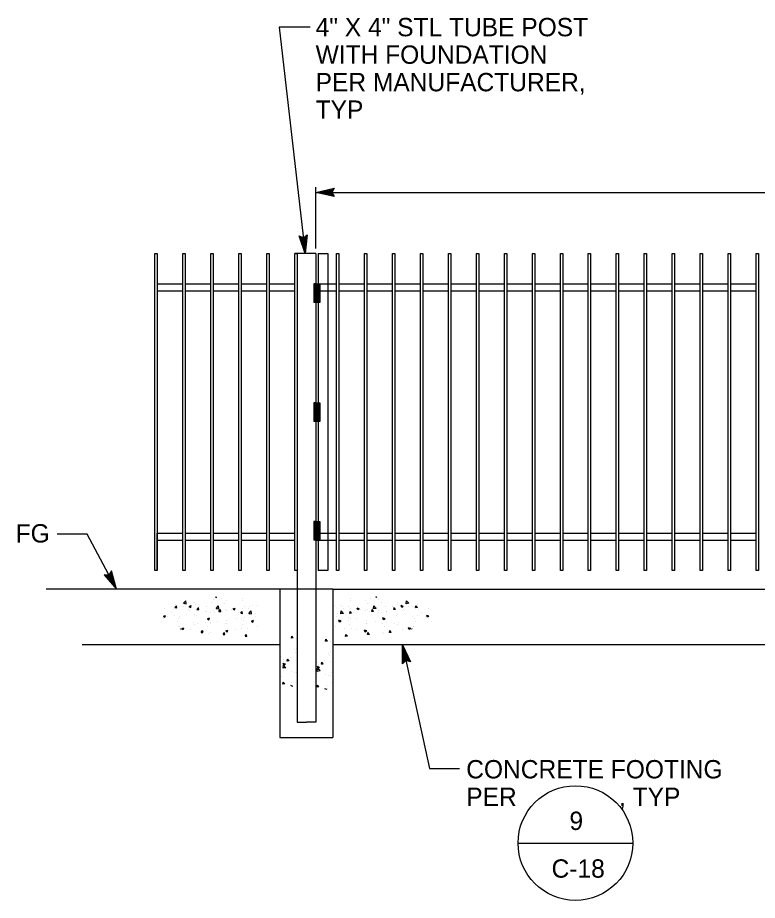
# Model space of a CAD drawing. Extents: x -121933 to -117742, y -103160 to -100084.
# Drawn here: x -118898.2 to -118656.4, y -103159.5 to -102870.8 of the extents above; entities that cross this region are included whole.
import ezdxf

# ---------------------------------------------------------------- set-up
doc = ezdxf.new("R2010")
doc.units = 0
for name, color, linetype in [('Erosion C (Lv35)', 7, 'Continuous'), ('G-MARK', 7, 'Continuous'), ('Misc CnstDet(22)', 7, 'Continuous')]:
    doc.layers.add(name, color=color, linetype=linetype)

# ---------------------------------------------------------------- blocks, each defined once
blk = doc.blocks.new('SC8415')
at = {"layer": 'Erosion C (Lv35)'}
for p, q in [((-1.69606, 1.76963), (-1.69579, 1.76945)), ((-1.69579, 1.76945), (-1.69573, 1.76963)), ((-1.69408, 1.76913), (-1.69408, 1.76913)), ((-1.68715, 1.76926), (-1.68715, 1.76926)), ((-1.70955, 1.76614), (-1.70906, 1.76672)), ((-1.70955, 1.76614), (-1.70894, 1.76608)), ((-1.70943, 1.76711), (-1.70943, 1.76711)), ((-1.70894, 1.76609), (-1.70906, 1.76672)), ((-1.70791, 1.76649), (-1.70791, 1.76649)), ((-1.70689, 1.76745), (-1.70689, 1.76745)), ((-1.70672, 1.76656), (-1.70672, 1.76656)), ((-1.70669, 1.76754), (-1.7059, 1.76836)), ((-1.70669, 1.76754), (-1.70579, 1.7674)), ((-1.70579, 1.7674), (-1.7059, 1.76836)), ((-1.70484, 1.76651), (-1.70412, 1.76679)), ((-1.70484, 1.76651), (-1.70433, 1.76617)), ((-1.70433, 1.76617), (-1.70412, 1.76679)), ((-1.70304, 1.76795), (-1.70304, 1.76795)), ((-1.70278, 1.76714), (-1.70278, 1.76714)), ((-1.70226, 1.7655), (-1.70177, 1.76608)), ((-1.70165, 1.76545), (-1.70177, 1.76609)), ((-1.7013, 1.76633), (-1.7013, 1.76633)), ((-1.69901, 1.76659), (-1.69901, 1.76659)), ((-1.6975, 1.7679), (-1.6975, 1.7679)), ((-1.69662, 1.7688), (-1.69662, 1.7688)), ((-1.69588, 1.7661), (-1.69588, 1.7661)), ((-1.69585, 1.76586), (-1.69506, 1.76668)), ((-1.69494, 1.76572), (-1.69506, 1.76668)), ((-1.69309, 1.7676), (-1.69309, 1.7676)), ((-1.69228, 1.76861), (-1.69228, 1.76861)), ((-1.68716, 1.76862), (-1.68716, 1.76862)), ((-1.68649, 1.76648), (-1.68649, 1.76648)), ((-1.68473, 1.76639), (-1.68473, 1.76639)), ((-1.68394, 1.76681), (-1.68394, 1.76681)), ((-1.682, 1.76664), (-1.682, 1.76664)), ((-1.71337, 1.76324), (-1.71266, 1.76351)), ((-1.71337, 1.76324), (-1.71287, 1.7629)), ((-1.71312, 1.76577), (-1.71312, 1.76577)), ((-1.71287, 1.7629), (-1.71266, 1.76351)), ((-1.7121, 1.7631), (-1.7121, 1.7631)), ((-1.71086, 1.76455), (-1.71086, 1.76455)), ((-1.71, 1.76543), (-1.71, 1.76543)), ((-1.70956, 1.76344), (-1.70956, 1.76344)), ((-1.70803, 1.7631), (-1.70803, 1.7631)), ((-1.70571, 1.76395), (-1.70571, 1.76395)), ((-1.70494, 1.76557), (-1.70494, 1.76557)), ((-1.70458, 1.7652), (-1.70458, 1.7652)), ((-1.7029, 1.76375), (-1.7029, 1.76375)), ((-1.7025, 1.76334), (-1.7025, 1.76334)), ((-1.70226, 1.7655), (-1.70165, 1.76545)), ((-1.6993, 1.76479), (-1.6993, 1.76479)), ((-1.69916, 1.76497), (-1.69916, 1.76497)), ((-1.69762, 1.76452), (-1.69762, 1.76452)), ((-1.69675, 1.76513), (-1.69675, 1.76513)), ((-1.69658, 1.76435), (-1.69658, 1.76435)), ((-1.69585, 1.76586), (-1.69494, 1.76572)), ((-1.69497, 1.76486), (-1.69449, 1.76545)), ((-1.69497, 1.76486), (-1.69437, 1.76481)), ((-1.69437, 1.76481), (-1.69448, 1.76545)), ((-1.69373, 1.76474), (-1.69373, 1.76474)), ((-1.6929, 1.76563), (-1.6929, 1.76563)), ((-1.69241, 1.76523), (-1.69241, 1.76523)), ((-1.69065, 1.76537), (-1.69065, 1.76537)), ((-1.69045, 1.76587), (-1.69045, 1.76587)), ((-1.69023, 1.7657), (-1.68952, 1.76597)), ((-1.69023, 1.7657), (-1.68973, 1.76536)), ((-1.68973, 1.76536), (-1.68952, 1.76597)), ((-1.68831, 1.76451), (-1.68831, 1.76451)), ((-1.68769, 1.76423), (-1.6872, 1.76481)), ((-1.68769, 1.76423), (-1.68708, 1.76417)), ((-1.68727, 1.76588), (-1.68727, 1.76588)), ((-1.68708, 1.76417), (-1.6872, 1.76481)), ((-1.68503, 1.76565), (-1.68503, 1.76565)), ((-1.685, 1.76418), (-1.68421, 1.765)), ((-1.685, 1.76418), (-1.6841, 1.76404)), ((-1.6841, 1.76404), (-1.68421, 1.765)), ((-1.68289, 1.76428), (-1.68289, 1.76428)), ((-1.68277, 1.76331), (-1.68277, 1.76331)), ((-1.71417, 1.76163), (-1.71417, 1.76163)), ((-1.71325, 1.76239), (-1.71325, 1.76239)), ((-1.70874, 1.7614), (-1.70874, 1.7614)), ((-1.70843, 1.76232), (-1.70843, 1.76232)), ((-1.70332, 1.76117), (-1.70332, 1.76117)), ((-1.70302, 1.76037), (-1.70302, 1.76037)), ((-1.70197, 1.76078), (-1.70197, 1.76078)), ((-1.69943, 1.76112), (-1.69943, 1.76112)), ((-1.69877, 1.76242), (-1.69806, 1.7627)), ((-1.69877, 1.76242), (-1.69827, 1.76208)), ((-1.69826, 1.76208), (-1.69806, 1.7627)), ((-1.6979, 1.76094), (-1.6979, 1.76094)), ((-1.69775, 1.76113), (-1.69775, 1.76113)), ((-1.69558, 1.76162), (-1.69558, 1.76162)), ((-1.6927, 1.7608), (-1.6927, 1.7608)), ((-1.69253, 1.76185), (-1.69253, 1.76185)), ((-1.69247, 1.76071), (-1.69247, 1.76071)), ((-1.68916, 1.76247), (-1.68916, 1.76247)), ((-1.6874, 1.7625), (-1.6874, 1.7625)), ((-1.68705, 1.76048), (-1.68705, 1.76048)), ((-1.68677, 1.76182), (-1.68677, 1.76182)), ((-1.68662, 1.7628), (-1.68662, 1.7628)), ((-1.68417, 1.76161), (-1.68346, 1.76188)), ((-1.68417, 1.76161), (-1.68366, 1.76127)), ((-1.68366, 1.76127), (-1.68346, 1.76188)), ((-1.70839, 1.75994), (-1.70839, 1.75994)), ((-1.70815, 1.75972), (-1.70815, 1.75972)), ((-1.70775, 1.75896), (-1.70765, 1.75908)), ((-1.70762, 1.7589), (-1.70765, 1.75908)), ((-1.70731, 1.75915), (-1.7066, 1.75942)), ((-1.70731, 1.75915), (-1.7068, 1.75881)), ((-1.7068, 1.75881), (-1.7066, 1.75942)), ((-1.70455, 1.75876), (-1.70455, 1.75876)), ((-1.70085, 1.75786), (-1.70036, 1.75844)), ((-1.70085, 1.75786), (-1.70025, 1.7578)), ((-1.70024, 1.75781), (-1.70036, 1.75844)), ((-1.69862, 1.75978), (-1.69862, 1.75978)), ((-1.69825, 1.75762), (-1.69825, 1.75762)), ((-1.69787, 1.75775), (-1.69787, 1.75775)), ((-1.69357, 1.75722), (-1.69308, 1.7578)), ((-1.69296, 1.75717), (-1.69307, 1.75781)), ((-1.69271, 1.75833), (-1.692, 1.75861)), ((-1.69271, 1.75833), (-1.6922, 1.75799)), ((-1.69265, 1.75847), (-1.69265, 1.75847)), ((-1.6922, 1.75799), (-1.69199, 1.75861)), ((-1.69183, 1.75846), (-1.69183, 1.75846)), ((-1.68929, 1.7588), (-1.68929, 1.7588)), ((-1.68752, 1.75912), (-1.68752, 1.75912)), ((-1.68544, 1.7593), (-1.68544, 1.7593)), ((-1.68224, 1.75988), (-1.68224, 1.75988)), ((-1.69357, 1.75722), (-1.69296, 1.75717)), ((-1.68628, 1.75658), (-1.68579, 1.75717)), ((-1.68628, 1.75658), (-1.68567, 1.75653)), ((-1.68567, 1.75653), (-1.68579, 1.75717))]:
    blk.add_line(p, q, dxfattribs=at)

msp = doc.modelspace()

# ---------------------------------------------------------------- linework, layer by layer
at = {"layer": 'G-MARK'}
for p, q in [((-118802.55, -102873.86), (-118812.69, -102873.86)), ((-118812.69, -102873.86), (-118804.14, -102947.98)), ((-118800.69, -102946.27), (-118800.69, -102926.23)), ((-118800.69, -102927.94), (-118794.69, -102926.61)), ((-118799.3, -102927.94), (-118794.92, -102926.97)), ((-118797.93, -102927.94), (-118795.1, -102927.32)), ((-118794.69, -102926.61), (-118795.49, -102927.94)), ((-118794.69, -102926.61), (-118794.69, -102926.61)), ((-118800.69, -102927.94), (-118459.12, -102927.94)), ((-118794.69, -102929.28), (-118800.69, -102927.94)), ((-118800.69, -102927.94), (-118800.69, -102927.94)), ((-118800.69, -102927.94), (-118456.45, -102927.94)), ((-118794.91, -102928.93), (-118799.31, -102927.94)), ((-118795.14, -102928.57), (-118797.93, -102927.94)), ((-118796.55, -102927.95), (-118795.34, -102927.68)), ((-118795.32, -102928.22), (-118796.55, -102927.95)), ((-118795.49, -102927.94), (-118794.69, -102929.28)), ((-118794.69, -102929.28), (-118794.69, -102929.28)), ((-118804.74, -102942.82), (-118803.5, -102941.87)), ((-118803.5, -102941.87), (-118804.14, -102947.98)), ((-118803.5, -102941.87), (-118803.5, -102941.87)), ((-118804.14, -102947.98), (-118806.15, -102942.17)), ((-118806.15, -102942.17), (-118806.15, -102942.17)), ((-118806.15, -102942.17), (-118804.74, -102942.82)), ((-118804.31, -102946.6), (-118805.77, -102942.37)), ((-118804.46, -102945.24), (-118805.4, -102942.5)), ((-118804.61, -102943.86), (-118805.02, -102942.69)), ((-118804.48, -102942.61), (-118804.61, -102943.86)), ((-118804.16, -102942.4), (-118804.46, -102945.24)), ((-118803.83, -102942.12), (-118804.3, -102946.61)), ((-118804.14, -102947.98), (-118804.14, -102947.98)), ((-118875.41, -103039.76), (-118885.2, -103039.76)), ((-118865.89, -103057.71), (-118875.41, -103039.76)), ((-118867.53, -103051.79), (-118868.33, -103053.12)), ((-118865.89, -103057.71), (-118867.53, -103051.79)), ((-118867.53, -103051.79), (-118867.53, -103051.79)), ((-118868.33, -103053.12), (-118869.89, -103053.04)), ((-118869.89, -103053.04), (-118869.89, -103053.04)), ((-118869.89, -103053.04), (-118865.89, -103057.71)), ((-118869.47, -103053.06), (-118866.54, -103056.49)), ((-118869.04, -103053.1), (-118867.19, -103055.27)), ((-118868.66, -103053.09), (-118867.84, -103054.05)), ((-118867.84, -103054.05), (-118868.17, -103052.86)), ((-118867.19, -103055.27), (-118867.96, -103052.48)), ((-118866.54, -103056.48), (-118867.74, -103052.16)), ((-118865.89, -103057.71), (-118865.89, -103057.71)), ((-118772.38, -103082.15), (-118772.36, -103076)), ((-118772.36, -103076), (-118763.49, -103116.38)), ((-118772.36, -103076), (-118772.36, -103076)), ((-118772.36, -103076), (-118769.77, -103081.57)), ((-118772.08, -103081.86), (-118772.06, -103077.35)), ((-118772.06, -103077.36), (-118770.17, -103081.42)), ((-118771.78, -103081.55), (-118771.77, -103078.7)), ((-118771.77, -103078.7), (-118770.55, -103081.32)), ((-118771.48, -103081.31), (-118771.47, -103080.05)), ((-118771.47, -103080.05), (-118770.95, -103081.17)), ((-118771.24, -103081.08), (-118772.38, -103082.15)), ((-118772.38, -103082.15), (-118772.38, -103082.15)), ((-118769.77, -103081.57), (-118771.24, -103081.08)), ((-118769.77, -103081.57), (-118769.77, -103081.57)), ((-118763.49, -103116.38), (-118753.69, -103116.38)), ((-118734.78, -103140.84), (-118697.08, -103140.84))]:
    msp.add_line(p, q, dxfattribs=at)
msp.add_circle((-118715.83, -103140.79), 18.75, dxfattribs=at)
at = {"layer": 'Misc CnstDet(22)'}
for p, q in [((-118853.29, -102947.98), (-118853.29, -102947.98)), ((-118843.76, -102947.98), (-118843.76, -102947.98)), ((-118834.62, -102947.98), (-118834.62, -102947.98)), ((-118800.72, -102947.98), (-118807.57, -102947.98)), ((-118807.19, -102947.98), (-118807.19, -102947.98)), ((-118800.72, -102947.98), (-118800.72, -103101.22)), ((-118799.92, -102947.98), (-118799.92, -103007.42)), ((-118799.92, -102947.98), (-118796.77, -102947.98)), ((-118796.77, -102947.98), (-118796.77, -103007.42)), ((-118852.53, -102957.89), (-118844.15, -102957.89)), ((-118843.38, -102957.89), (-118835, -102957.89)), ((-118834.24, -102957.89), (-118825.86, -102957.89)), ((-118825.1, -102957.89), (-118816.71, -102957.89)), ((-118815.95, -102957.89), (-118807.57, -102957.89)), ((-118801.35, -102957.89), (-118801.35, -102963.99)), ((-118800.75, -102957.89), (-118801.35, -102957.89)), ((-118801.15, -102957.89), (-118801.15, -102963.99)), ((-118800.95, -102957.89), (-118800.95, -102963.99)), ((-118800.75, -102957.89), (-118800.75, -102963.99)), ((-118800.72, -102957.89), (-118793.91, -102957.89)), ((-118793.15, -102957.89), (-118784.77, -102957.89)), ((-118784.01, -102957.89), (-118775.63, -102957.89)), ((-118774.86, -102957.89), (-118766.48, -102957.89)), ((-118765.72, -102957.89), (-118757.34, -102957.89)), ((-118756.58, -102957.89), (-118748.19, -102957.89)), ((-118747.43, -102957.89), (-118739.05, -102957.89)), ((-118738.29, -102957.89), (-118729.91, -102957.89)), ((-118729.14, -102957.89), (-118720.76, -102957.89)), ((-118720, -102957.89), (-118711.62, -102957.89)), ((-118710.86, -102957.89), (-118702.47, -102957.89)), ((-118701.71, -102957.89), (-118693.33, -102957.89)), ((-118692.57, -102957.89), (-118684.19, -102957.89)), ((-118683.42, -102957.89), (-118675.04, -102957.89)), ((-118674.28, -102957.89), (-118665.9, -102957.89)), ((-118665.14, -102957.89), (-118656.75, -102957.89)), ((-118852.53, -102960.17), (-118844.15, -102960.17)), ((-118843.38, -102960.17), (-118835, -102960.17)), ((-118834.24, -102960.17), (-118825.86, -102960.17)), ((-118825.1, -102960.17), (-118816.71, -102960.17)), ((-118815.95, -102960.17), (-118807.57, -102960.17)), ((-118806.81, -102960.17), (-118806.81, -103101.22)), ((-118800.72, -102960.17), (-118793.91, -102960.17)), ((-118793.15, -102960.17), (-118784.77, -102960.17)), ((-118784.01, -102960.17), (-118775.63, -102960.17)), ((-118774.86, -102960.17), (-118766.48, -102960.17)), ((-118765.72, -102960.17), (-118757.34, -102960.17)), ((-118756.58, -102960.17), (-118748.19, -102960.17)), ((-118747.43, -102960.17), (-118739.05, -102960.17)), ((-118738.29, -102960.17), (-118729.91, -102960.17)), ((-118729.14, -102960.17), (-118720.76, -102960.17)), ((-118720, -102960.17), (-118711.62, -102960.17)), ((-118710.86, -102960.17), (-118702.47, -102960.17)), ((-118701.71, -102960.17), (-118693.33, -102960.17)), ((-118692.57, -102960.17), (-118684.19, -102960.17)), ((-118683.42, -102960.17), (-118675.04, -102960.17)), ((-118674.28, -102960.17), (-118665.9, -102960.17)), ((-118665.14, -102960.17), (-118656.75, -102960.17)), ((-118800.75, -102963.99), (-118801.35, -102963.99)), ((-118801.35, -102996.75), (-118801.35, -103002.85)), ((-118800.75, -102996.75), (-118801.35, -102996.75)), ((-118801.15, -102996.75), (-118801.15, -103002.85)), ((-118800.95, -102996.75), (-118800.95, -103002.85)), ((-118800.75, -102996.75), (-118800.75, -103002.85)), ((-118800.75, -103002.85), (-118801.35, -103002.85)), ((-118799.92, -103007.42), (-118799.92, -103051.61)), ((-118801.35, -103035.61), (-118801.35, -103041.71)), ((-118800.75, -103035.61), (-118801.35, -103035.61)), ((-118801.15, -103035.61), (-118801.15, -103041.71)), ((-118800.95, -103035.61), (-118800.95, -103041.71)), ((-118800.75, -103035.61), (-118800.75, -103041.71)), ((-118852.53, -103051.61), (-118852.53, -103039.42)), ((-118852.53, -103039.42), (-118844.15, -103039.42)), ((-118843.38, -103039.42), (-118835, -103039.42)), ((-118834.24, -103039.42), (-118825.86, -103039.42)), ((-118825.1, -103039.42), (-118816.71, -103039.42)), ((-118815.95, -103039.42), (-118807.57, -103039.42)), ((-118800.72, -103039.42), (-118793.91, -103039.42)), ((-118793.15, -103039.42), (-118784.77, -103039.42)), ((-118784.01, -103039.42), (-118775.63, -103039.42)), ((-118774.86, -103039.42), (-118766.48, -103039.42)), ((-118765.72, -103039.42), (-118757.34, -103039.42)), ((-118756.58, -103039.42), (-118748.19, -103039.42)), ((-118747.43, -103039.42), (-118739.05, -103039.42)), ((-118738.29, -103039.42), (-118729.91, -103039.42)), ((-118729.14, -103039.42), (-118720.76, -103039.42)), ((-118720, -103039.42), (-118711.62, -103039.42)), ((-118710.86, -103039.42), (-118702.47, -103039.42)), ((-118701.71, -103039.42), (-118693.33, -103039.42)), ((-118692.57, -103039.42), (-118684.19, -103039.42)), ((-118683.42, -103039.42), (-118675.04, -103039.42)), ((-118674.28, -103039.42), (-118665.9, -103039.42)), ((-118665.14, -103039.42), (-118656.75, -103039.42)), ((-118852.53, -103041.71), (-118844.15, -103041.71)), ((-118843.38, -103041.71), (-118835, -103041.71)), ((-118834.24, -103041.71), (-118825.86, -103041.71)), ((-118825.1, -103041.71), (-118816.71, -103041.71)), ((-118815.95, -103041.71), (-118807.57, -103041.71)), ((-118800.75, -103041.71), (-118801.35, -103041.71)), ((-118800.72, -103041.71), (-118793.91, -103041.71)), ((-118793.15, -103041.71), (-118784.77, -103041.71)), ((-118784.01, -103041.71), (-118775.63, -103041.71)), ((-118774.86, -103041.71), (-118766.48, -103041.71)), ((-118765.72, -103041.71), (-118757.34, -103041.71)), ((-118756.58, -103041.71), (-118748.19, -103041.71)), ((-118747.43, -103041.71), (-118739.05, -103041.71)), ((-118738.29, -103041.71), (-118729.91, -103041.71)), ((-118729.14, -103041.71), (-118720.76, -103041.71)), ((-118720, -103041.71), (-118711.62, -103041.71)), ((-118710.86, -103041.71), (-118702.47, -103041.71)), ((-118701.71, -103041.71), (-118693.33, -103041.71)), ((-118692.57, -103041.71), (-118684.19, -103041.71)), ((-118683.42, -103041.71), (-118675.04, -103041.71)), ((-118674.28, -103041.71), (-118665.9, -103041.71)), ((-118665.14, -103041.71), (-118656.75, -103041.71)), ((-118853.29, -103051.61), (-118853.29, -103051.61)), ((-118796.77, -103051.61), (-118799.92, -103051.61)), ((-118812.43, -103057.71), (-118888.83, -103057.71)), ((-118855.01, -103057.71), (-118877.35, -103057.71)), ((-118875.63, -103057.71), (-118875.63, -103057.71)), ((-118855.01, -103057.71), (-118860.95, -103057.71)), ((-118859.24, -103057.71), (-118859.24, -103057.71)), ((-118853.29, -103057.71), (-118853.29, -103057.71)), ((-118853.29, -103057.71), (-118853.29, -103057.71)), ((-118812.43, -103057.71), (-118812.43, -103094.29)), ((-118795.1, -103057.71), (-118812.43, -103057.71)), ((-118795.1, -103057.71), (-118795.1, -103106.29)), ((-118795.1, -103057.71), (-118622.28, -103057.71)), ((-118808.66, -103073.75), (-118808.55, -103073.12)), ((-118808.06, -103073.69), (-118808.66, -103073.75)), ((-118808.06, -103073.69), (-118808.55, -103073.12)), ((-118807.17, -103073.89), (-118807.17, -103073.89)), ((-118797.49, -103074.76), (-118797.38, -103074.13)), ((-118796.89, -103074.71), (-118797.49, -103074.76)), ((-118796.89, -103074.71), (-118797.37, -103074.13)), ((-118796, -103074.91), (-118796, -103074.91)), ((-118812.43, -103076), (-118877.12, -103076)), ((-118812.24, -103076.47), (-118812.24, -103076.47)), ((-118807.6, -103077.64), (-118807.6, -103077.64)), ((-118807.05, -103077.22), (-118807.05, -103077.22)), ((-118795.27, -103075.21), (-118795.27, -103075.21)), ((-118623.66, -103076), (-118795.1, -103076)), ((-118812.12, -103079.8), (-118812.12, -103079.8)), ((-118810.05, -103081.27), (-118809.93, -103080.64)), ((-118809.45, -103081.22), (-118809.93, -103080.64)), ((-118809.72, -103080.57), (-118809.72, -103080.57)), ((-118809.04, -103080.04), (-118809.04, -103080.04)), ((-118807.33, -103078.38), (-118807.33, -103078.38)), ((-118806.93, -103080.55), (-118806.93, -103080.55)), ((-118796.43, -103078.65), (-118796.43, -103078.65)), ((-118796.16, -103079.39), (-118796.16, -103079.39)), ((-118795.88, -103078.24), (-118795.88, -103078.24)), ((-118812, -103083.13), (-118812, -103083.13)), ((-118811.39, -103083.61), (-118811.28, -103082.66)), ((-118810.5, -103083.48), (-118811.39, -103083.61)), ((-118811.13, -103082.64), (-118811.34, -103082.04)), ((-118810.63, -103082.31), (-118811.33, -103082.04)), ((-118811.29, -103080.75), (-118811.29, -103080.75)), ((-118810.5, -103083.48), (-118811.28, -103082.66)), ((-118811.15, -103081.38), (-118811.15, -103081.38)), ((-118810.63, -103082.31), (-118811.13, -103082.64)), ((-118809.45, -103081.22), (-118810.05, -103081.27)), ((-118799.46, -103083.32), (-118800.16, -103083.05)), ((-118799.96, -103083.65), (-118800.16, -103083.05)), ((-118800.11, -103081.76), (-118800.11, -103081.76)), ((-118799.98, -103082.4), (-118799.98, -103082.4)), ((-118799.46, -103083.32), (-118799.96, -103083.66)), ((-118798.88, -103082.28), (-118798.76, -103081.65)), ((-118798.28, -103082.23), (-118798.88, -103082.28)), ((-118798.28, -103082.23), (-118798.76, -103081.66)), ((-118798.55, -103081.59), (-118798.55, -103081.59)), ((-118797.87, -103081.05), (-118797.87, -103081.05)), ((-118795.76, -103081.57), (-118795.76, -103081.57)), ((-118812.39, -103085.35), (-118812.39, -103085.35)), ((-118811.88, -103086.46), (-118811.88, -103086.46)), ((-118811.16, -103084.37), (-118811.16, -103084.37)), ((-118808.65, -103084.69), (-118808.65, -103084.69)), ((-118807.71, -103085.07), (-118807.71, -103085.07)), ((-118807.06, -103085.12), (-118807.06, -103085.12)), ((-118806.81, -103083.88), (-118806.81, -103083.88)), ((-118800.22, -103084.63), (-118800.11, -103083.68)), ((-118799.33, -103084.49), (-118800.22, -103084.63)), ((-118799.33, -103084.49), (-118800.11, -103083.68)), ((-118799.99, -103085.38), (-118799.99, -103085.38)), ((-118797.48, -103085.71), (-118797.48, -103085.71)), ((-118796.54, -103086.09), (-118796.54, -103086.09)), ((-118795.88, -103086.14), (-118795.88, -103086.14)), ((-118795.63, -103084.89), (-118795.63, -103084.89)), ((-118812.32, -103087.81), (-118812.32, -103087.81)), ((-118811.44, -103088.79), (-118811.32, -103088.16)), ((-118810.84, -103088.74), (-118811.44, -103088.79)), ((-118810.84, -103088.74), (-118811.32, -103088.16)), ((-118808.2, -103089.56), (-118808.9, -103089.29)), ((-118808.53, -103088.31), (-118808.53, -103088.31)), ((-118806.68, -103087.21), (-118806.68, -103087.21)), ((-118800.27, -103089.8), (-118800.15, -103089.18)), ((-118799.67, -103089.75), (-118800.15, -103089.18)), ((-118797.36, -103089.32), (-118797.36, -103089.32)), ((-118795.51, -103088.22), (-118795.51, -103088.22)), ((-118799.67, -103089.75), (-118800.27, -103089.8)), ((-118797.03, -103090.57), (-118797.73, -103090.3)), ((-118812.43, -103094.29), (-118812.43, -103106.29)), ((-118806.81, -103101.22), (-118803.76, -103101.22)), ((-118800.72, -103101.22), (-118803.76, -103101.22)), ((-118812.43, -103106.29), (-118795.1, -103106.29))]:
    msp.add_line(p, q, dxfattribs=at)
for points in [[(-118852.53, -103051.61), (-118853.29, -103051.61), (-118853.29, -102947.98), (-118852.53, -102947.98)], [(-118843.38, -103051.61), (-118844.15, -103051.61), (-118844.15, -102947.98), (-118843.38, -102947.98)], [(-118834.24, -103051.61), (-118835, -103051.61), (-118835, -102947.98), (-118834.24, -102947.98)], [(-118825.1, -103051.61), (-118825.86, -103051.61), (-118825.86, -102947.98), (-118825.1, -102947.98)], [(-118815.95, -103051.61), (-118816.71, -103051.61), (-118816.71, -102947.98), (-118815.95, -102947.98)], [(-118806.81, -103051.61), (-118807.57, -103051.61), (-118807.57, -102947.98), (-118806.81, -102947.98)], [(-118793.15, -103051.61), (-118793.91, -103051.61), (-118793.91, -102947.98), (-118793.15, -102947.98)], [(-118784.01, -103051.61), (-118784.77, -103051.61), (-118784.77, -102947.98), (-118784.01, -102947.98)], [(-118774.86, -103051.61), (-118775.63, -103051.61), (-118775.63, -102947.98), (-118774.86, -102947.98)], [(-118765.72, -103051.61), (-118766.48, -103051.61), (-118766.48, -102947.98), (-118765.72, -102947.98)], [(-118756.58, -103051.61), (-118757.34, -103051.61), (-118757.34, -102947.98), (-118756.58, -102947.98)], [(-118747.43, -103051.61), (-118748.19, -103051.61), (-118748.19, -102947.98), (-118747.43, -102947.98)], [(-118738.29, -103051.61), (-118739.05, -103051.61), (-118739.05, -102947.98), (-118738.29, -102947.98)], [(-118729.14, -103051.61), (-118729.91, -103051.61), (-118729.91, -102947.98), (-118729.14, -102947.98)], [(-118720, -103051.61), (-118720.76, -103051.61), (-118720.76, -102947.98), (-118720, -102947.98)], [(-118710.86, -103051.61), (-118711.62, -103051.61), (-118711.62, -102947.98), (-118710.86, -102947.98)], [(-118701.71, -103051.61), (-118702.47, -103051.61), (-118702.47, -102947.98), (-118701.71, -102947.98)], [(-118692.57, -103051.61), (-118693.33, -103051.61), (-118693.33, -102947.98), (-118692.57, -102947.98)], [(-118683.42, -103051.61), (-118684.19, -103051.61), (-118684.19, -102947.98), (-118683.42, -102947.98)], [(-118674.28, -103051.61), (-118675.04, -103051.61), (-118675.04, -102947.98), (-118674.28, -102947.98)], [(-118665.14, -103051.61), (-118665.9, -103051.61), (-118665.9, -102947.98), (-118665.14, -102947.98)], [(-118655.99, -103051.61), (-118656.75, -103051.61), (-118656.75, -102947.98), (-118655.99, -102947.98)], [(-118799.38, -102963.99), (-118800.75, -102963.99), (-118800.75, -102957.89), (-118799.38, -102957.89)], [(-118799.58, -102963.79), (-118800.55, -102963.79), (-118800.55, -102958.09), (-118799.58, -102958.09)], [(-118799.78, -102963.59), (-118800.35, -102963.59), (-118800.35, -102958.29), (-118799.78, -102958.29)], [(-118799.98, -102963.39), (-118800.15, -102963.39), (-118800.15, -102958.49), (-118799.98, -102958.49)], [(-118799.38, -103002.85), (-118800.75, -103002.85), (-118800.75, -102996.75), (-118799.38, -102996.75)], [(-118799.58, -103002.65), (-118800.55, -103002.65), (-118800.55, -102996.95), (-118799.58, -102996.95)], [(-118799.78, -103002.45), (-118800.35, -103002.45), (-118800.35, -102997.15), (-118799.78, -102997.15)], [(-118799.98, -103002.25), (-118800.15, -103002.25), (-118800.15, -102997.35), (-118799.98, -102997.35)], [(-118799.38, -103041.71), (-118800.75, -103041.71), (-118800.75, -103035.61), (-118799.38, -103035.61)], [(-118799.58, -103041.51), (-118800.55, -103041.51), (-118800.55, -103035.81), (-118799.58, -103035.81)], [(-118799.78, -103041.31), (-118800.35, -103041.31), (-118800.35, -103036.01), (-118799.78, -103036.01)], [(-118799.98, -103041.11), (-118800.15, -103041.11), (-118800.15, -103036.21), (-118799.98, -103036.21)]]:
    msp.add_lwpolyline(points, close=True, dxfattribs=at)
msp.add_lwpolyline([(-118796.77, -103007.42), (-118796.77, -103051.61)], dxfattribs=at)

# ---------------------------------------------------------------- block references
at = {"layer": 'Misc CnstDet(22)', "xscale": 984.251968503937, "yscale": 984.251968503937}
msp.add_blockref('SC8415', (-117164.11, -104802.07), dxfattribs=at)
at = {"layer": 'Misc CnstDet(22)', "xscale": 984.251968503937, "yscale": -984.251968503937, "rotation": 180}
msp.add_blockref('SC8415', (-120450.1, -104802.07), dxfattribs=at)

# ---------------------------------------------------------------- texts
at = {"layer": 'Misc CnstDet(22)'}
for s, p in [('4" X 4" STL TUBE POST ', (-118800.76, -102876.89)), ('WITH FOUNDATION', (-118800.76, -102885.89)), ('PER MANUFACTURER,', (-118800.76, -102894.89)), ('TYP', (-118800.76, -102903.89)), ('FG', (-118898.82, -103042.49)), ('CONCRETE FOOTING', (-118751.53, -103119.65)), ('PER               , TYP', (-118751.53, -103128.65)), ('9', (-118717.79, -103136.52)), ('C-18', (-118723.63, -103152.13))]:
    msp.add_text(s, height=6, dxfattribs=at).set_placement(p)

doc.saveas('drawing.dxf')
